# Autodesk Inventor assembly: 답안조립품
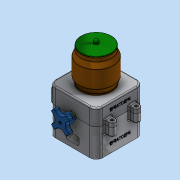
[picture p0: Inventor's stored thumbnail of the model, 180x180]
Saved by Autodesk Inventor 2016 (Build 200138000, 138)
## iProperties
Created: 2018-01
Part Number: 답안조립품
Material: 일반
Document SubType Name: Assembly
Designer: Administrator
Author: Administrator
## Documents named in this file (9)
- C:\Users\Administrator\Desktop\480108V1016\답안조립품.iam
- C:\Users\Administrator\Desktop\480108V1016\본체.ipt
- C:\Users\Administrator\Desktop\480108V1016\핸들축.ipt
- C:\Users\Administrator\Desktop\480108V1016\핸들.ipt
- C:\Users\Administrator\Desktop\480108V1016\볼트 M3x12.ipt
- C:\Users\Administrator\Desktop\480108V1016\본체커버.ipt
- C:\Users\Administrator\Desktop\480108V1016\볼트 M4x12.ipt
- C:\Users\Administrator\Desktop\480108V1016\용기.ipt
- C:\Users\Administrator\Desktop\480108V1016\용기캡.ipt
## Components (2 placed, 2 different names)
1. 핸들축:1
2. 핸들:1
